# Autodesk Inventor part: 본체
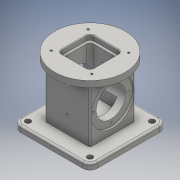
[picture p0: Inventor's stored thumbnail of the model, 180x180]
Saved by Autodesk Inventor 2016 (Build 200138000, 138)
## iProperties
Created: 2021-05
Part Number: 본체
Material: 일반
Document SubType Name: Modeling
Designer: CAD16
Density: 1 g/cm^3
Appearance: 기본값
Author: CAD16
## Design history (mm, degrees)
sketch "스케치1"
  geometry: L1 (-37, 37)-(37, 37); L2 (37, 37)-(37, -37); L3 (37, -37)-(-37, -37); L4 (-37, -37)-(-37, 37); L5 (-37, 37)-(37, -37); L6 (37, 37)-(-37, -37); 1 further point
  constraints: 12 end point, 2 midpoint, 2 parallel, 1 horizontal, 1 perpendicular
  dimensions: "d0" = 74 distance of L1.end L2.end; "d3" = 74 distance of L1.start L1.end
extrude "돌출1" new body sketch "스케치1" distance "d1" = 108; taper "d2" = 0 deg
sketch "스케치2"
  geometry: L1 (-62.5, 62.5)-(62.5, 62.5); L2 (62.5, 62.5)-(62.5, -62.5); L3 (62.5, -62.5)-(-62.5, -62.5); L4 (-62.5, -62.5)-(-62.5, 62.5); L5 (-62.5, 62.5)-(62.5, -62.5); L6 (62.5, 62.5)-(-62.5, -62.5); 1 further point
  constraints: 12 end point, 2 midpoint, 2 parallel, 1 horizontal, 1 perpendicular
  dimensions: "d4" = 125 distance of L1.start L1.end; "d5" = 125 distance of L1.end L2.end
sketch "스케치3"
  geometry: C1 r 57.5 at (0, 0); 1 further point
  constraints: 1 centre point, 1 coincident
  dimensions: "d8" = 115 diameter of C1
extrude "돌출3" join sketch "스케치3" distance "d9" = 10; taper "d10" = 0 deg
extrude "돌출4" join sketch "스케치2" distance "d11" = 10; taper "d12" = 0 deg
sketch "스케치4"
  geometry: L1 (37, 10)-(37, 98) reference; L2 (-37, 10)-(-37, 98) reference; L3 (37, 54)-(-37, 54); L4 (-37, 54)-(-37, 89); L5 (-37, 89)-(-34, 89); L6 (-34, 89)-(-34, 78); L7 (-34, 78)-(34, 78); L8 (34, 78)-(34, 89); L9 (34, 89)-(37, 89); L10 (37, 54)-(37, 89); 1 further point
  constraints: 16 end point, 4 point on line, 3 perpendicular, 2 midpoint, 1 collinear, 1 horizontal
  dimensions: "d13" = 3 distance of L8.end L9.end; "d14" = 3 distance of L4.end L5.end; "d15" = 70 diameter of L9 L3; "d16" = 48 diameter of L7 L3
revolve "회전1" sketch "스케치4" stored, may be unused: angle "d17" = 90 deg
sketch "스케치5"
  geometry: L1 (-44, -57.5)-(-44, 57.5) reference; C1 r 35 at (0, 0) reference; 2 further points
  constraints: 1 horizontal alignment
  dimensions: "d18" = 29 distance of C1.centre point (-29, 0)
sketch "스케치6"
  geometry: L1 (0, 0)-(0, 18); L2 (0, 18)-(24.826, 18); L3 (24.826, 18)-(28, 0); L4 (28, 0)-(0, 0); L5 (62.5, 0)-(-62.5, 0) reference; L6 (28, 0)-(0, 0)
  constraints: 10 end point, 2 collinear, 1 perpendicular, 1 vertical
  dimensions: "d36" = 18 distance between parallel lines of L4 L2; "d37" = 80 deg angle of L4 L3; "d38" = 56 diameter of L3.end L1
hole "구멍1" sketch "스케치5" diameter "d19" = 3.242; stored, may be unused: countersink angle "d23" = 90 deg, drill point angle "d25" = 118 deg; dims "d20" = 8, "d21" = 4, "d22" = 2, "d24" = 10
revolve "회전2" stored, may be unused: angle "d39" = 90 deg
fillet "모깎기1" dims "d40" = 12
hole "구멍2" diameter "d43" = 9; stored, may be unused: countersink angle "d47" = 90 deg, drill point angle "d49" = 118 deg; dims "d41" = 10, "d42" = 10, "d44" = 8, "d45" = 4, "d46" = 2, "d48" = 9
sketch "스케치7"
  geometry: L1 (-26, -26)-(26, -26); L2 (26, -26)-(26, 26); L3 (26, 26)-(-26, 26); L4 (-26, 26)-(-26, -26); L5 (-26, -26)-(26, 26); L6 (26, -26)-(-26, 26); 1 further point
  constraints: 12 end point, 2 midpoint, 2 parallel, 1 horizontal, 1 perpendicular
  dimensions: "d54" = 52 distance of L3.end L1.start; "d55" = 52 distance of L2.end L3.end (= d54)
extrude "돌출5" cut sketch "스케치7" distance "d56" = 8; taper "d57" = 0 deg
sketch "스케치8"
  geometry: L1 (-22, -22)-(22, -22); L2 (22, -22)-(22, 22); L3 (22, 22)-(-22, 22); L4 (-22, 22)-(-22, -22); L5 (-22, -22)-(22, 22); L6 (22, -22)-(-22, 22); 1 further point
  constraints: 12 end point, 2 midpoint, 2 parallel, 1 horizontal, 1 perpendicular
  dimensions: "d58" = 44 distance of L3.end L1.start; "d59" = 44 distance of L2.end L3.end (= d58)
extrude "돌출6" cut sketch "스케치8" distance "d60" = 74; taper "d61" = 0 deg
sketch "스케치9"
  geometry: L1 (-13.5, -98)-(87.5, -98) reference; 4 further points
  constraints: 2 midpoint, 2 vertical alignment
  dimensions: "d62" = 37 distance of point (37, -98) point (37, -61)
hole "구멍3" sketch "스케치9" at (37, -61) diameter "d63" = 4.134; stored, may be unused: countersink angle "d67" = 90 deg, drill point angle "d69" = 118 deg; dims "d64" = 10, "d65" = 4, "d66" = 2, "d68" = 14.2
sketch "스케치10"
  geometry: L1 (-13.5, -98)-(87.5, -98) reference; C1 r 2.067 at (37, -61) reference; 2 further points
  constraints: 1 vertical alignment
  dimensions: "d70" = 43 distance of C1.centre point (37, -18)
hole "구멍4" sketch "스케치10" at (37, -18) diameter "d71" = 4.134; stored, may be unused: countersink angle "d75" = 90 deg, drill point angle "d77" = 118 deg; dims "d72" = 10, "d73" = 4, "d74" = 2, "d76" = 14.2
sketch "스케치11"
  geometry: 2 further points
  dimensions: "d78" = 33 horizontal distance of point (0, 0) point (33, 30); "d93" = 30 vertical distance of point (0, 0) point (33, 30)
fillet "모깎기2" dims "d79" = 6
hole "구멍5" sketch "스케치11" diameter "d80" = 3.242; stored, may be unused: countersink angle "d84" = 90 deg, drill point angle "d86" = 118 deg; dims "d81" = 8, "d82" = 4, "d83" = 2, "d85" = 10
chamfer "모따기1" distance "d100" = 1; stored, may be unused: second distance "d101" = 2, angle "d102" = 45 deg
fillet "모깎기3" dims "d103" = 3
fillet "모깎기4" dims "d104" = 3
sketch "스케치12"
  geometry: L1 (62.5, -50.5)-(62.5, 50.5) reference; L2 (50.5, 62.5)-(-50.5, 62.5) reference; L3 (-62.5, 50.5)-(-62.5, -50.5) reference; 5 further points
  constraints: 3 midpoint, 1 horizontal alignment, 1 other
  dimensions: "d110" = 55 horizontal distance of point (0, 62.5) point (-55, 0)
fillet "모깎기5" dims "d108" = 3
feature "엠보싱2" dims "d111" = 0.5, "d112" = 0
node "솔리드1"
pattern_circular "원형 패턴1" dims angle "d27" = 360 deg
mirror "대칭1"
pattern_linear "직사각형 패턴1"
pattern_linear "직사각형 패턴3" dims "d96" = 66
